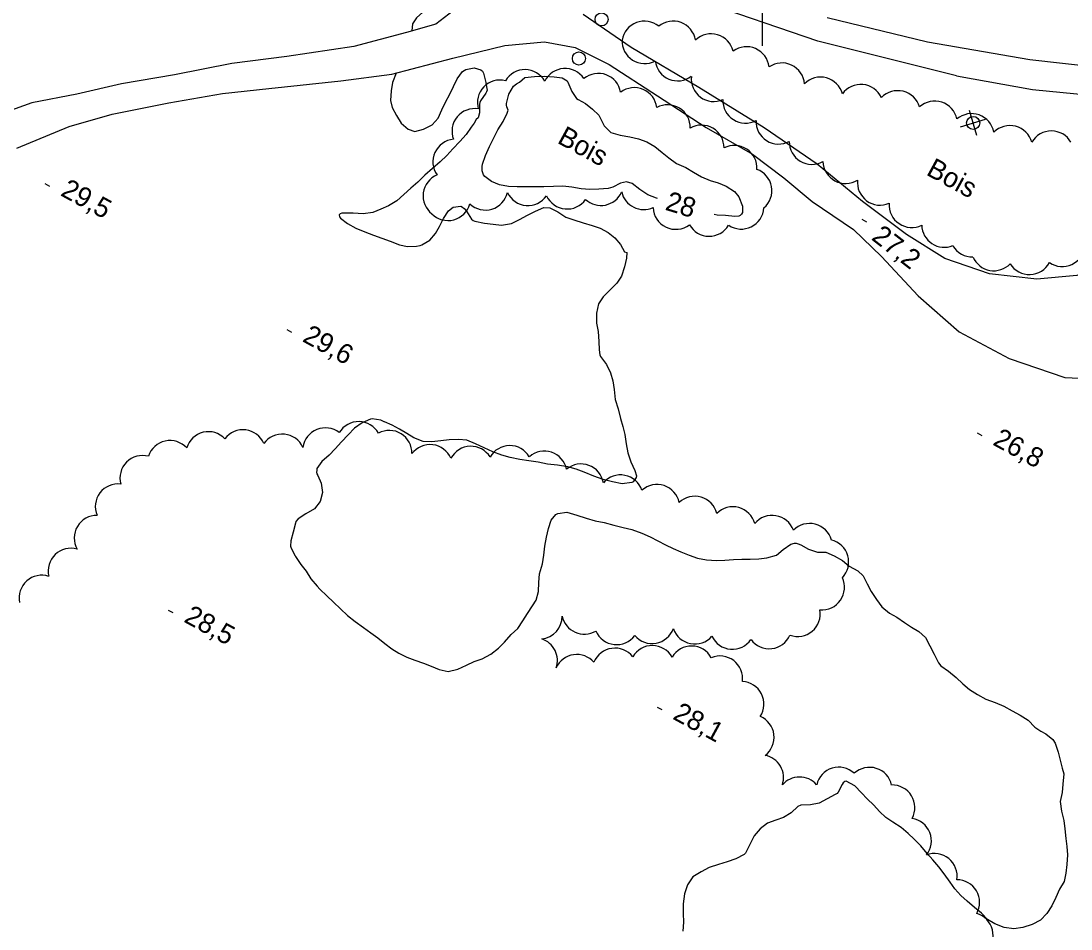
# Model space of a CAD drawing. Extents: x 219136 to 222520, y 5421589 to 5424530.
# Drawn here: x 219886.7 to 220047.2, y 5423654.9 to 5423793.8 of the extents above; entities that cross this region are included whole.
import ezdxf

# ---------------------------------------------------------------- set-up
doc = ezdxf.new("R2010")
doc.units = 0
for name, color, linetype in [('Level 19', 7, 'Continuous'), ('Level 2', 7, 'Continuous'), ('Level 21', 7, 'Continuous'), ('Level 3', 7, 'Continuous'), ('Level 36', 7, 'Continuous'), ('Level 44', 7, 'Continuous'), ('Level 61', 7, 'Continuous')]:
    doc.layers.add(name, color=color, linetype=linetype)

msp = doc.modelspace()

# ---------------------------------------------------------------- linework, layer by layer
at = {"layer": 'Level 19'}
for points in [[(219952.77, 5423795.36), (219950.09, 5423793.35), (219945.62, 5423792.08), (219937.55, 5423789.93), (219927.33, 5423788.36), (219918.92, 5423787.29), (219910.14, 5423785.57), (219902.05, 5423784.19), (219895.2, 5423782.62), (219888.33, 5423781.32), (219879.37, 5423778.07), (219872.36, 5423773.57), (219866.34, 5423768.48), (219860.57, 5423764.75)], [(220042, 5423754.33), (220034.79, 5423755.15), (220027.93, 5423757.47), (220022.07, 5423761.18), (220015.35, 5423766.19), (220008.41, 5423771.94), (220000.33, 5423777.47), (219990.31, 5423783.62), (219980, 5423789.75), (219972.63, 5423794.81)], [(219886.03, 5423774.37), (219894.04, 5423777.68), (219900.59, 5423779.56), (219909.3, 5423781.28), (219917.48, 5423782.74), (219924.55, 5423783.48), (219935.6, 5423784.68), (219943.4, 5423785.69), (219952.71, 5423788.11), (219960.64, 5423790.08), (219966.72, 5423790.62), (219971.44, 5423789.78), (219976.61, 5423787.18), (219984.02, 5423782.37), (219991.44, 5423777.55), (219998.56, 5423773.45), (220003.32, 5423769.85), (220007.66, 5423766.22), (220013.96, 5423761.93), (220018.26, 5423757.78), (220023.86, 5423751.8), (220030.15, 5423746.3), (220037.78, 5423742.2), (220046.29, 5423739.31), (220057.34, 5423738.78)], [(220072.65, 5423781.08), (220074.02, 5423778.11), (220074.71, 5423775.45), (220072.75, 5423772.03), (220068.22, 5423767.11), (220060.67, 5423761.3), (220052.88, 5423756.68), (220048.13, 5423754.91), (220042, 5423754.33)]]:
    msp.add_lwpolyline(points, dxfattribs=at)
at = {"layer": 'Level 2'}
for points in [[(219949.43, 5423797.72), (219949.25, 5423796.21), (219948.11, 5423795.14), (219947.15, 5423794.28), (219946.55, 5423793.36), (219946.45, 5423792.32)], [(219944.04, 5423785.86), (219943.46, 5423784.41), (219943.26, 5423783.12), (219943.19, 5423781.65), (219943.44, 5423780.57), (219944.07, 5423779.37), (219944.8, 5423778.2), (219945.88, 5423777.26), (219946.89, 5423776.93), (219948.24, 5423777.28), (219949.53, 5423777.94), (219950.45, 5423778.96), (219951.03, 5423780.21), (219951.59, 5423781.38), (219952.26, 5423782.64), (219952.79, 5423783.82), (219953.37, 5423784.97), (219954.2, 5423786.08), (219954.69, 5423786.39), (219955.98, 5423786.67), (219957, 5423786.35), (219957.23, 5423786.14), (219957.39, 5423785.85), (219957.76, 5423784.42), (219957.85, 5423783.74)], [(219961.21, 5423768.52), (219959.87, 5423768.75), (219958.61, 5423769.28), (219957.59, 5423770.05), (219957.42, 5423770.31), (219957.21, 5423770.89), (219957.17, 5423771.54), (219957.23, 5423771.91), (219957.69, 5423773.22), (219958.3, 5423774.61), (219958.86, 5423775.76), (219959.61, 5423777.15), (219960.41, 5423778.46), (219961.04, 5423779.7), (219961.15, 5423780.19), (219961.09, 5423780.44), (219960.97, 5423780.7), (219960.91, 5423780.95), (219960.92, 5423781.21), (219961.27, 5423782.6), (219961.99, 5423783.85), (219962.42, 5423784.21), (219962.92, 5423784.47), (219963.72, 5423785.15)], [(219963.72, 5423785.15), (219965.21, 5423785.33), (219966.71, 5423785.38), (219968.18, 5423785.29), (219969.44, 5423785.11), (219970.17, 5423784.66), (219970.31, 5423784.45), (219970.9, 5423783.04), (219971.61, 5423781.97), (219971.87, 5423781.79), (219973, 5423781.18), (219974.07, 5423780.35), (219975.04, 5423779.39), (219975.18, 5423779.1), (219975.86, 5423777.8), (219976.88, 5423776.78), (219978.29, 5423776.33), (219979.77, 5423776.08), (219981.1, 5423775.8), (219982.38, 5423775.33), (219983.62, 5423774.61), (219984.72, 5423773.72), (219985.74, 5423772.89), (219986.93, 5423772.03), (219988.36, 5423771.4), (219989.53, 5423770.69), (219990.72, 5423769.97), (219992.04, 5423769.43), (219993.27, 5423769.04), (219994.51, 5423768.57), (219995.78, 5423767.75), (219996.47, 5423766.93), (219997.01, 5423765.47), (219997.01, 5423764.55), (219996.87, 5423764.27), (219996.65, 5423764.05), (219996.42, 5423763.95), (219995.83, 5423763.9), (219994.39, 5423764.09), (219993.13, 5423764.13), (219992.69, 5423764.21)], [(219957.85, 5423783.74), (219957.95, 5423783.25), (219957.87, 5423782.99), (219957.75, 5423782.77), (219956.94, 5423781.61), (219956.84, 5423781.36), (219956.81, 5423781.1), (219956.77, 5423779.76), (219956.58, 5423779.02), (219956.26, 5423778.74), (219955.98, 5423778.17), (219955.98, 5423778.17)], [(219955.98, 5423778.17), (219955.53, 5423777.56), (219954.74, 5423776.46), (219953.77, 5423775.36), (219952.72, 5423774.27), (219951.78, 5423773.23), (219950.76, 5423772.26), (219949.58, 5423771.28), (219948.41, 5423770.26), (219947.36, 5423769.19), (219946.29, 5423768.23), (219945.2, 5423767.27), (219944.17, 5423766.31), (219942.87, 5423765.55), (219941.69, 5423765.04), (219940.49, 5423764.54), (219938.99, 5423764.33), (219937.45, 5423764.44), (219935.74, 5423764.42), (219935.5, 5423764.32), (219935.31, 5423764.15), (219935.4, 5423763.86), (219935.55, 5423763.66), (219936.62, 5423762.82), (219937.86, 5423762.15), (219939.24, 5423761.55), (219940.6, 5423761.06), (219941.87, 5423760.59), (219943.13, 5423760.14), (219944.53, 5423759.59), (219945.77, 5423759.35), (219947.13, 5423759.38), (219947.7, 5423759.46)], [(219983.99, 5423766.66), (219983.87, 5423766.7), (219982.54, 5423767.21), (219981.31, 5423768.04), (219980.11, 5423768.97), (219979.28, 5423769.21), (219978.36, 5423769.01), (219977.16, 5423768.42), (219976.46, 5423768.22), (219975.05, 5423768.12), (219973.65, 5423768.04), (219972.31, 5423768.17), (219970.89, 5423768.4), (219969.55, 5423768.53), (219968.08, 5423768.48), (219966.62, 5423768.43), (219965.26, 5423768.44), (219963.99, 5423768.45), (219962.54, 5423768.46), (219961.21, 5423768.52)], [(219947.7, 5423759.46), (219947.96, 5423759.58), (219949.21, 5423760.31), (219950.04, 5423761.32), (219950.68, 5423762.39), (219951.29, 5423763.61), (219952.03, 5423764.8), (219952.76, 5423765.32), (219953.91, 5423765.48), (219954.19, 5423765.34), (219954.44, 5423765.16), (219954.81, 5423764.74), (219955.58, 5423763.5), (219955.83, 5423763.32), (219956.06, 5423763.22), (219957.56, 5423762.89), (219958.88, 5423762.73), (219960.13, 5423762.58), (219961.7, 5423762.86), (219962.91, 5423763.45), (219964.14, 5423764.1), (219965.37, 5423764.74), (219966.63, 5423765.29), (219967.53, 5423765.24), (219968.75, 5423764.61), (219969.99, 5423763.82), (219971.23, 5423763.39), (219972.63, 5423762.96), (219974, 5423762.52), (219975.22, 5423762.12), (219976.46, 5423761.48), (219977.47, 5423760.65), (219978.36, 5423759.63), (219978.98, 5423758.49), (219979.34, 5423758.39)], [(219979.34, 5423758.39), (219979.25, 5423757.52), (219978.98, 5423756.22), (219978.5, 5423754.8), (219977.79, 5423753.7), (219976.77, 5423752.68), (219975.69, 5423751.64), (219975.01, 5423750.54), (219974.67, 5423749.14), (219974.69, 5423747.58), (219974.95, 5423746.35), (219975.06, 5423744.8), (219975.08, 5423743.53), (219975.17, 5423742.78), (219975.29, 5423742.52), (219976.2, 5423741.27), (219976.81, 5423739.98), (219977.18, 5423738.78), (219977.37, 5423737.45), (219977.54, 5423735.95), (219977.99, 5423734.52), (219978.37, 5423733.01), (219978.71, 5423731.8), (219979.02, 5423730.57), (219979.21, 5423729.15), (219979.45, 5423727.79), (219979.92, 5423726.37), (219980.55, 5423725.08), (219980.82, 5423724.23), (219980.76, 5423723.99), (219980.3, 5423723.33), (219980.06, 5423723.23), (219978.58, 5423723.05), (219977.11, 5423723.35), (219975.7, 5423723.71), (219974.25, 5423724.2), (219972.81, 5423724.79), (219971.56, 5423725.29), (219970.3, 5423725.61), (219968.74, 5423725.9), (219967.19, 5423726.05), (219965.74, 5423726.34), (219964.31, 5423726.57), (219962.97, 5423726.76), (219961.47, 5423727.08), (219960.18, 5423727.4), (219958.81, 5423727.91), (219957.51, 5423728.55), (219956.16, 5423729.13), (219954.84, 5423729.73), (219953.58, 5423729.8), (219952.14, 5423729.74), (219950.89, 5423729.6), (219949.52, 5423729.45), (219948.19, 5423729.51), (219946.73, 5423730.04), (219945.65, 5423730.74), (219944.55, 5423731.41), (219943.41, 5423732), (219942.25, 5423732.5), (219942.2, 5423732.51)], [(219942.2, 5423732.51), (219941.68, 5423732.74), (219940.38, 5423732.98), (219940.13, 5423732.94), (219938.85, 5423732.37), (219937.68, 5423731.53), (219936.7, 5423730.54), (219935.7, 5423729.43), (219934.74, 5423728.37), (219933.81, 5423727.42), (219932.7, 5423726.43), (219931.92, 5423725.35), (219931.92, 5423725.09), (219931.85, 5423724.82), (219931.9, 5423724.56), (219932.04, 5423724.31), (219932.6, 5423723.11), (219932.76, 5423721.71), (219932.44, 5423720.33), (219931.54, 5423719.18), (219930.23, 5423718.44), (219929.04, 5423717.69), (219928.72, 5423717.29), (219928.66, 5423717.01), (219928.29, 5423715.65), (219927.92, 5423714.33), (219927.88, 5423713.48), (219928.01, 5423713.21), (219928.61, 5423712.03), (219928.67, 5423711.91)], [(219966.8, 5423713.5), (219967.05, 5423714.88), (219967.34, 5423716.21), (219967.74, 5423717.45), (219968.48, 5423718.35), (219968.77, 5423718.48), (219970.15, 5423718.68), (219971.69, 5423718.24), (219973.09, 5423717.78), (219974.48, 5423717.39), (219975.87, 5423717.11), (219977.33, 5423716.72), (219978.76, 5423716.37), (219980.09, 5423716.02), (219981.6, 5423715.46), (219982.87, 5423714.92), (219984.08, 5423714.33), (219985.25, 5423713.71), (219986.39, 5423713.16), (219987.59, 5423712.63), (219988.83, 5423712.1), (219990.14, 5423711.65), (219991.51, 5423711.38), (219993.01, 5423711.28), (219994.29, 5423711.36), (219995.61, 5423711.44), (219996.92, 5423711.49), (219998.2, 5423711.53), (219999.48, 5423711.55), (220000.74, 5423711.71), (220002.18, 5423712.14), (220003.23, 5423712.99), (220004.4, 5423713.79), (220004.97, 5423713.94), (220005.23, 5423713.93), (220005.52, 5423713.86), (220005.92, 5423713.69), (220007.1, 5423713.02), (220008.47, 5423712.56), (220009.73, 5423712.6)], [(219931.95, 5423707.4), (219932.38, 5423706.93), (219933.46, 5423705.92), (219934.48, 5423704.93), (219935.51, 5423703.93), (219936.6, 5423702.88), (219937.79, 5423701.99), (219939.03, 5423701.06), (219940.15, 5423700.24), (219941.25, 5423699.46), (219942.31, 5423698.63), (219943.39, 5423697.81), (219944.46, 5423697.12), (219945.7, 5423696.51), (219946.91, 5423696.05), (219948.22, 5423695.6), (219949.41, 5423695.14), (219950.63, 5423694.62), (219951.99, 5423694.34), (219953.48, 5423694.69), (219954.78, 5423695.3), (219955.99, 5423695.86), (219957.22, 5423696.26), (219958.54, 5423696.98), (219959.67, 5423697.88), (219960.63, 5423698.82), (219961.61, 5423699.98), (219962.67, 5423700.91), (219963.41, 5423702.06), (219964.12, 5423703.22), (219964.9, 5423704.36), (219965.47, 5423705.22), (219965.81, 5423706.57), (219965.84, 5423707.92), (219965.96, 5423709.26), (219966.42, 5423710.78), (219966.65, 5423712.13), (219966.8, 5423713.5)], [(220009.73, 5423712.6), (220011.03, 5423712.04), (220012.3, 5423711.31), (220013.34, 5423710.44), (220014.63, 5423709.7), (220015.44, 5423708.97), (220016.07, 5423707.75), (220016.69, 5423706.54), (220017.49, 5423705.32), (220018.3, 5423704.2), (220019.47, 5423703.25), (220020.59, 5423702.62), (220021.79, 5423701.84), (220022.83, 5423701.12), (220023.97, 5423700.45), (220024.98, 5423699.54), (220025.65, 5423698.26), (220026.29, 5423697), (220026.97, 5423695.65), (220027.34, 5423695.17), (220028.5, 5423694.36), (220029.67, 5423693.4), (220030.71, 5423692.45), (220031.74, 5423691.57), (220032.92, 5423690.83), (220034.23, 5423690.12), (220035.66, 5423689.6), (220036.96, 5423689), (220038.23, 5423688.3), (220039.49, 5423687.67), (220040.67, 5423686.87), (220041.73, 5423685.83), (220042.64, 5423685.2), (220043.39, 5423684.81), (220044.45, 5423683.91), (220044.8, 5423683.39), (220045.3, 5423682.01), (220045.57, 5423680.77), (220045.88, 5423679.55), (220046.12, 5423678.65), (220046.01, 5423677.12), (220045.88, 5423675.84), (220045.57, 5423674.43), (220045.79, 5423672.97), (220046.12, 5423671.55), (220046.28, 5423670.26), (220046.46, 5423668.81), (220046.6, 5423667.55), (220046.68, 5423666.27), (220046.62, 5423664.83), (220046.46, 5423663.48), (220046.17, 5423662.2), (220045.49, 5423661.02), (220044.92, 5423659.75), (220044.3, 5423658.47), (220043.55, 5423657.3), (220042.6, 5423656.3), (220041.3, 5423655.63), (220039.87, 5423655.17), (220038.51, 5423654.96), (220037.02, 5423655.19), (220035.6, 5423655.72), (220034.49, 5423656.38), (220033.56, 5423657.34), (220032.48, 5423658.25)], [(219928.67, 5423711.91), (219929.44, 5423710.7), (219930.26, 5423709.65), (219931, 5423708.5), (219931.95, 5423707.4)], [(220032.48, 5423658.25), (220031.36, 5423659.21), (220030.4, 5423660.05), (220029.48, 5423661.11), (220028.74, 5423662.13), (220027.86, 5423663.38), (220027.04, 5423664.44), (220026.1, 5423665.51), (220025.24, 5423666.51), (220024.27, 5423667.67), (220023.28, 5423668.67), (220022.36, 5423669.56), (220021.27, 5423670.49), (220020.02, 5423671.3), (220018.91, 5423672.02), (220017.96, 5423672.91), (220017.09, 5423673.87), (220016.09, 5423674.84), (220015.2, 5423675.77), (220014.17, 5423676.85), (220012.88, 5423677.56), (220012.64, 5423677.48), (220012.42, 5423677.3), (220012.23, 5423677.06), (220011.62, 5423675.88), (220011.46, 5423675.69), (220011.2, 5423675.5), (220009.96, 5423674.85), (220008.71, 5423674.2), (220007.4, 5423673.92), (220005.95, 5423673.86), (220005.45, 5423673.69), (220004.46, 5423672.73), (220003.28, 5423672.01), (220002.09, 5423671.6), (220000.85, 5423671.12), (219999.69, 5423670.24), (219998.77, 5423669.19), (219998.14, 5423667.87), (219997.47, 5423666.52), (219997.26, 5423666.34), (219995.97, 5423665.7), (219994.66, 5423665.22), (219993.31, 5423664.83), (219991.93, 5423664.36), (219990.68, 5423663.71), (219989.43, 5423662.93), (219988.6, 5423661.72), (219988.15, 5423660.3), (219987.93, 5423658.81), (219987.92, 5423657.32), (219988, 5423655.97), (219987.87, 5423654.62)]]:
    msp.add_lwpolyline(points, dxfattribs=at)
at = {"layer": 'Level 21'}
for points in [[(220029.74, 5423785.41), (220008.55, 5423790.75), (219990.32, 5423796.97), (219977.46, 5423802.7), (219962.15, 5423810.86), (219947.86, 5423819.91), (219928.35, 5423832.02), (219904.66, 5423847.85), (219879.7, 5423863.82), (219857.91, 5423878.68), (219837.55, 5423892.54), (219809.64, 5423910.71), (219782.71, 5423928.01), (219755.89, 5423945.47), (219725.67, 5423965.76), (219705.12, 5423978.77)], [(220148.61, 5423785.14), (220144.31, 5423787.85), (220138.96, 5423790.42), (220134.01, 5423790.72), (220128.95, 5423790.04), (220124.86, 5423790.87), (220106.98, 5423787.75), (220090.46, 5423785.91), (220077.35, 5423785.17), (220060.49, 5423785.67), (220040.97, 5423787.86), (220025.3, 5423790.58), (220009.96, 5423794.29)], [(220029.74, 5423785.41), (220041.37, 5423783.32), (220054.9, 5423782.03), (220067.42, 5423781.4), (220077.74, 5423780.76), (220089.66, 5423781.26), (220102.39, 5423782.79), (220125.81, 5423785.97), (220135.91, 5423787.29), (220141.11, 5423787.08), (220144.35, 5423785.28), (220148.97, 5423781.97), (220152.77, 5423778.1), (220154.61, 5423774.17), (220159.46, 5423762.7), (220165.2, 5423748.18), (220169.89, 5423736.91), (220175.06, 5423725.32), (220180.06, 5423715.93), (220185.29, 5423706.17), (220189.37, 5423698.33), (220192.27, 5423693.15)]]:
    msp.add_lwpolyline(points, dxfattribs=at)
at = {"layer": 'Level 3'}
for p, q in [((219890.33, 5423768.95), (219891.03, 5423768.56)), ((220015.27, 5423763.5), (220015.97, 5423763.11)), ((219927.32, 5423746.63), (219928.03, 5423746.24)), ((220032.89, 5423730.82), (220033.59, 5423730.43)), ((219909.19, 5423703.73), (219909.89, 5423703.34)), ((219983.95, 5423688.89), (219984.66, 5423688.49))]:
    msp.add_line(p, q, dxfattribs=at)
at = {"layer": 'Level 36'}
for p, q in [((220032.84, 5423776.3), (220031.71, 5423780.13)), ((220030.36, 5423777.65), (220034.19, 5423778.78))]:
    msp.add_line(p, q, dxfattribs=at)
for centre in [(219975.45, 5423794.06), (219971.99, 5423788.08), (220032.28, 5423778.22)]:
    msp.add_circle(centre, 1, dxfattribs=at)
at = {"layer": 'Level 44'}
for centre, start, end in [((219982, 5423790.33), 50.5705, 170.5705), ((219986.4, 5423790.34), 9.5054, 129.5054), ((219992.21, 5423788.4), 13.5877, 133.5877), ((219982.04, 5423790.76), 177.6091, 297.6091), ((219997.62, 5423786.42), 6.2634, 126.2634), ((219963.75, 5423782.92), 29.3788, 149.3788), ((219969.87, 5423783.09), 33.7742, 153.7742), ((219987.09, 5423788.12), 187.0993, 307.0993), ((220003.03, 5423783.94), 4.4353, 124.4353), ((219959.93, 5423781.32), 76.0553, 196.0553), ((219974.96, 5423782.34), 9.5734, 129.5734), ((219992.62, 5423784.96), 173.5389, 293.5389), ((220008.94, 5423781.77), 15.1438, 135.1438), ((219980.47, 5423780.16), 7.0823, 127.0823), ((220015.1, 5423780.66), 24.5176, 144.5176), ((220020.75, 5423779.7), 16.2105, 136.2105), ((219997.46, 5423781.65), 177.6798, 297.6798), ((220026.41, 5423778.1), 12.1917, 132.1918), ((219956.04, 5423776.95), 80.5554, 200.5554), ((219985.55, 5423777.54), 358.4373, 118.4373), ((220002.53, 5423778.46), 178.0284, 298.0284), ((220032.03, 5423776.19), 10.186, 130.186), ((219990.72, 5423774.43), 359.5218, 119.5218), ((220037.9, 5423774.36), 15.3189, 135.3189), ((220044.24, 5423773.54), 29.9281, 149.9281), ((219953.12, 5423772.28), 95.434, 215.434), ((220007.62, 5423775.35), 179.0852, 299.0852), ((219995.76, 5423771.31), 356.9504, 116.9504), ((220012.77, 5423772.43), 181.8382, 301.8382), ((219951.62, 5423767.07), 112.4264, 232.4264), ((219998.04, 5423767.87), 310.1791, 70.1791), ((220018.04, 5423769.11), 173.6535, 293.6535), ((219957.69, 5423768.36), 226.7798, 346.7798), ((219964.19, 5423769.05), 205.3723, 325.3723), ((219970.19, 5423768.52), 204.5765, 324.5765), ((219975.36, 5423769.06), 227.2925, 336.103), ((219981.9, 5423768.44), 192.9645, 294.2863), ((219951.97, 5423766.76), 224.5807, 344.5807), ((219986.79, 5423765.41), 182.1174, 307.3238), ((220022.89, 5423765.69), 175.9972, 295.9972), ((219996.82, 5423765.45), 236.1494, 356.1494), ((219991.91, 5423764.35), 209.2839, 329.2839), ((220027.87, 5423762.66), 181.3453, 292.1408), ((220032.17, 5423761.18), 210.0341, 271.3397), ((220045.9, 5423759.71), 235.5159, 355.5159), ((220035.44, 5423759.08), 203.1706, 316.1536), ((220040.89, 5423758.5), 211.6336, 331.6336), ((219933.21, 5423728.13), 52.0401, 172.0401), ((219938.32, 5423729.09), 29.1918, 149.1918), ((219915.34, 5423727.54), 43.4838, 163.4838), ((219920.62, 5423727.84), 22.8893, 142.8893), ((219926.63, 5423727.17), 24.5694, 144.5694), ((219943, 5423727.74), 358.5181, 118.5181), ((219909.46, 5423726.19), 42.3218, 162.3218), ((219949.23, 5423725.57), 23.1965, 143.1965), ((219955.47, 5423725.31), 31.9109, 151.9109), ((219961.42, 5423725.42), 30.3584, 150.3584), ((219905.27, 5423723.9), 75.2243, 195.2243), ((219966.71, 5423724.58), 11.5135, 131.5135), ((219972.32, 5423722.61), 9.7917, 129.7917), ((219978.35, 5423720.93), 19.0378, 139.0378), ((219901.49, 5423719.55), 82.7434, 202.7434), ((219983.93, 5423719.47), 11.613, 131.613), ((219989.72, 5423717.67), 13.901, 133.901), ((219995.53, 5423716.06), 15.0469, 135.0469), ((219898.27, 5423714.75), 89.4807, 209.4807), ((220001.54, 5423714.74), 20.2366, 140.2366), ((220007.27, 5423713.51), 15.5328, 135.5328), ((220009.78, 5423711.07), 316.1763, 76.1763), ((219894.29, 5423709.71), 73.8496, 193.8496), ((219889.85, 5423705.59), 71.844, 191.844), ((220009.14, 5423707.2), 265.1268, 25.1268), ((219965.96, 5423702.75), 275.8235, 0.4834), ((219972.81, 5423703.5), 192.0209, 300.4834), ((220005.44, 5423703.14), 250.2278, 10.2278), ((219977.75, 5423701.9), 203.4527, 323.4527), ((219983.18, 5423702.06), 220.0281, 340.0281), ((219989.72, 5423701.99), 198.7785, 318.7785), ((219995.46, 5423701.19), 205.1638, 325.1638), ((220001.09, 5423701.26), 216.4276, 336.4276), ((219965.24, 5423696.01), 340.9956, 72.0209), ((219977.5, 5423694.44), 38.0474, 158.0474), ((219983.22, 5423694.83), 29.6374, 149.6374), ((219989.2, 5423694.76), 29.0034, 149.0034), ((219971.68, 5423693.47), 40.9956, 155.8235), ((219993.56, 5423693.24), 352.5873, 112.5873), ((219996.82, 5423689.33), 327.1278, 87.1278), ((219998.38, 5423684.26), 306.9416, 66.9416), ((219999.82, 5423678.09), 341.3439, 79.4799), ((220011.72, 5423676.23), 46.9169, 166.9169), ((220016.43, 5423676.21), 12.6012, 132.6012), ((220005.74, 5423674.73), 41.3439, 139.4799), ((220019.9, 5423673.51), 331.621, 91.621), ((220022.43, 5423668.44), 321.2542, 81.2542), ((220026.37, 5423663.03), 350.9501, 110.9501), ((220029.81, 5423659.02), 330.3383, 90.3383), ((220031.87, 5423653.98), 314.0779, 74.0779)]:
    msp.add_arc(centre, 3.46, start, end, dxfattribs=at)
at = {"layer": 'Level 61'}
msp.add_lwpolyline([(220000, 5423810), (220000, 5423800), (220000, 5423790)], dxfattribs=at)

# ---------------------------------------------------------------- texts
at = {"layer": 'Level 2'}
msp.add_text('28', height=3, rotation=343.0825, dxfattribs=at).set_placement((219985.04, 5423764.97))
at = {"layer": 'Level 3'}
for s, rotation, p in [('29,5', 331.383, (219892.57, 5423767.2)), ('27,2', 322.1441, (220016.58, 5423760.47)), ('29,6', 331.383, (219929.56, 5423744.88)), ('26,8', 331.383, (220035.13, 5423729.07)), ('28,5', 331.383, (219911.43, 5423701.99)), ('28,1', 331.383, (219986.19, 5423687.14))]:
    msp.add_text(s, height=3, rotation=rotation, dxfattribs=at).set_placement(p)
at = {"layer": 'Level 44'}
for p in [(219968.53, 5423775.24), (220024.95, 5423770.36)]:
    msp.add_text('Bois', height=3, rotation=331.3547, dxfattribs=at).set_placement(p)

doc.saveas('drawing.dxf')
